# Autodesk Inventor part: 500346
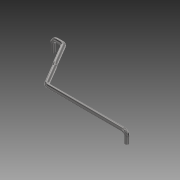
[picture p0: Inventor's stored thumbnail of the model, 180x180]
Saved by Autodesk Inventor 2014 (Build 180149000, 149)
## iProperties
Created: 2007-11
Part Number: 500346
Document SubType Name: Modeling
Designer: TH
Density: 7.85 g/cm^3
Mass: 28.3508 g
Surface Area: 30.7052 cm^2
Volume: 3.61157 cm^3
Material: Steel
Description: SIDE LINK BAR
Appearance: Steel - Polished
Component Category: Side Component
Author: TH
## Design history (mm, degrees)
sketch "Sketch1"
  geometry: C1 r 2.38 at (0, 0); 1 further point
  constraints: 1 centre point, 1 coincident
  dimensions: "d0" = 4.76 diameter of C1
sketch "Sketch2"
  geometry: L1 (0, 0)-(0, 8); L2 (5, 13)-(100, 13); A1 r 5 centre (5, 8) between (5, 13) and (0, 8); 1 further point
  constraints: 4 end point, 2 point on circle, 2 point on line, 2 tangent, 1 centre point, 1 perpendicular, 1 vertical
  dimensions: "d1" = 13 distance of L1.start point (0, 13); "d2" = 100 distance of point (0, 13) L2.end; "d3" = 5 radius of A1
sweep "Sweep1" sketch "Sketch1", "Sketch2" dims "d4" = 0
workplane "Work Plane1"
  workaxis "Work Axis1"
sketch "Sketch3"
  geometry: C1 r 2.38 at (0, 0) reference; 1 further point
sketch "Sketch4"
  geometry: L1 (95, 2.38)-(95, -2.38) reference; L2 (-5, -14.189)-(-5, 68.471) reference; L3 (-32.173, 0)-(141.376, 0) reference; L4 (112.25, 24.456)-(99.309, 2.464); L5 (130, 54.621)-(126.53, 56.663); A1 r 5 centre (95, 5) between (95, 0) and (99.309, 2.464); 1 further point
  constraints: 4 end point, 3 point on line, 2 point on circle, 1 centre point, 1 perpendicular, 1 tangent
  dimensions: "d6" = 10 diameter of A1; "d11" = 35 distance of L5.start L4.start; "d44" = 54.62059 vertical distance of L5.start A1.start; "d45" = 35 horizontal distance of L5.start A1.start
sweep "Sweep2" sketch "Sketch3", "Sketch4" dims "d12" = 0
workplane "Work Plane2"
  workaxis "Work Axis2"
sketch "Sketch5"
  geometry: C1 r 2.38 at (0, 0) reference; 1 further point
sketch "Sketch6"
  geometry: L1 (66.604, 13)-(-116.013, 13) reference; L2 (-116.013, 13)-(66.604, 13) reference; L3 (66.604, 13)-(-116.013, 13) reference; L4 (0, 2.38)-(0, -2.38) reference; L5 (40.516, -1.2)-(30.266, -1.2); L6 (25.516, -5)-(30.266, 3.8); L7 (25.516, 2.38)-(25.516, -2.38) reference; L8 (0, 2.38)-(0, -2.38) reference; A1 r 5 centre (25.516, -5) between (27.891, -0.6) and (25.516, 0); A2 r 5 centre (30.266, 3.8) between (27.891, -0.6) and (30.266, -1.2); 2 further points
  constraints: 5 end point, 5 point on circle, 2 centre point, 2 midpoint, 2 tangent, 1 perpendicular, 1 point on line
  dimensions: "d16" = 10 diameter of A1; "d20" = 10 diameter of A2; "d22" = 1.2 distance from line of A1.end L5; "d23" = 15 distance from line of L7 L5.start
sweep "Sweep3" sketch "Sketch5", "Sketch6" dims "d21" = 0
workaxis "Work Axis3"
sketch "Sketch7"
  geometry: C1 r 2.38 at (0, 0) reference; 1 further point
workplane "Work Plane3"
sketch "Sketch8"
  geometry: L1 (-101.674, 116.493)-(4.563, -64.048) reference; L2 (34.742, -7.634)-(31.7, -2.464); L3 (10.25, 2.38)-(10.25, -2.38) reference; L4 (10.25, 0)-(27.391, 0); A1 r 5 centre (27.391, -5) between (31.7, -2.464) and (27.391, 0); 2 further points
  constraints: 4 end point, 2 point on circle, 2 tangent, 1 centre point, 1 parallel, 1 perpendicular, 1 point on line
  dimensions: "d27" = 5 distance of L2.start point (37.278, -11.943); "d28" = 5 radius of A1; "d41" = 27.02761 horizontal distance of point (37.278, -11.943) L4.start; "d42" = 11.94284 vertical distance of L4.start point (37.278, -11.943)
sweep "Sweep4" sketch "Sketch8" dims "d29" = 0
workplane "Work Plane4"
  workaxis "Work Axis4"
sketch "Sketch10"
  geometry: C1 r 2.38 at (0, 0) reference; 1 further point
sketch "Sketch11"
  geometry: L1 (5.998, 2.38)-(5.998, -2.38) reference; L2 (-137.859, -6.236)-(-137.859, 20.756) reference; L3 (42.488, 14.2)-(-170.694, 14.2) reference; L4 (10.998, 15)-(10.998, 5); L5 (5.998, 0)-(5.998, 0); A1 r 5 centre (5.998, 5) between (5.998, 0) and (10.998, 5); 1 further point
  constraints: 5 end point, 2 perpendicular, 2 point on circle, 2 tangent, 1 centre point
  dimensions: "d33" = 5 radius of A1; "d34" = 15 vertical distance of L4.start L5.start; "d43" = 5 horizontal distance of L4.start L5.start
sweep "Sweep5" sketch "Sketch10", "Sketch11" dims "d35" = 0
workplane "Work Plane5"
  workaxis "Work Axis5"
body "Solid1"
node "Projected Loop1"
node "Projected Loop2"
node "Projected Loop4"
other parameters: "d5" = 90 deg, "d13" = 90 deg, "d24" = 0, "d30" = 90 deg, "d40" = 90 deg
